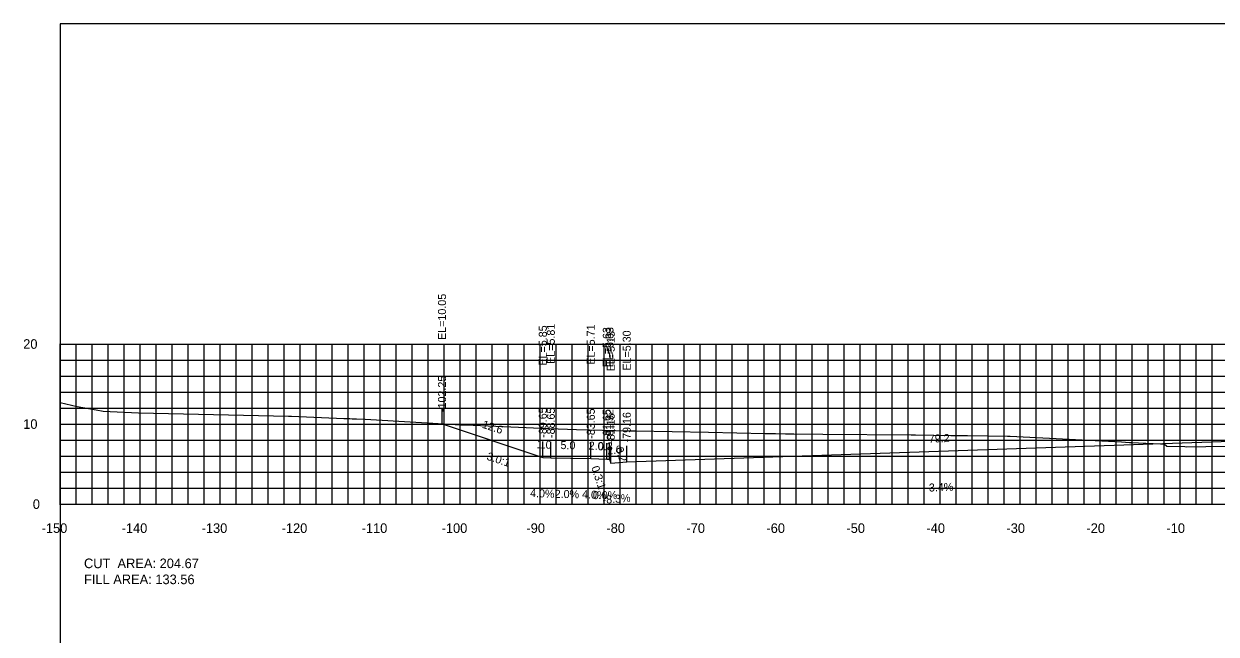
# Model space of a CAD drawing. Extents: x 1797419 to 1809236, y 248759 to 251512.
# Drawn here: x 1805876.5 to 1806025.5, y 250531 to 250607.3 of the extents above; entities that cross this region are included whole.
import ezdxf

# ---------------------------------------------------------------- set-up
doc = ezdxf.new("R2010")
doc.units = 0
for name, color, linetype in [('10', 7, 'Continuous'), ('3', 7, 'Continuous'), ('31', 7, 'Continuous'), ('4', 7, 'Continuous'), ('60', 7, 'Continuous'), ('ANNO-TXT', 7, 'Continuous'), ('CL-CNST', 7, 'Continuous'), ('Level 62', 7, 'Continuous'), ('M-ROADS', 7, 'Continuous')]:
    doc.layers.add(name, color=color, linetype=linetype)

msp = doc.modelspace()

# ---------------------------------------------------------------- linework, layer by layer
for p, q in [((1805928.75, 250557.3), (1805928.75, 250559.3)), ((1805941.35, 250553.1), (1805941.35, 250555.1)), ((1805942.35, 250553.06), (1805942.35, 250555.06)), ((1805947.35, 250552.96), (1805947.35, 250554.96)), ((1805949.35, 250552.88), (1805949.35, 250554.88)), ((1805949.68, 250552.88), (1805949.68, 250554.88)), ((1805951.84, 250552.55), (1805951.84, 250554.55)), ((1805949.84, 250552.38), (1805949.84, 250554.38))]:
    msp.add_line(p, q)
msp.add_lwpolyline([(1805881, 250417.26), (1806181, 250417.26), (1806181, 250607.26), (1805881, 250607.26)], close=True)
at = {"layer": '60'}
for p, q in [((1805880.94, 250567.26), (1805881, 250567.26)), ((1805881, 250547.26), (1805881, 250567.26)), ((1805880.94, 250557.26), (1805881, 250557.26)), ((1805880.94, 250547.26), (1805881, 250547.26)), ((1805881, 250547.26), (1806181, 250547.26)), ((1805881, 250547.2), (1805881, 250547.26)), ((1805891, 250547.2), (1805891, 250547.26)), ((1805901, 250547.2), (1805901, 250547.26)), ((1805911, 250547.2), (1805911, 250547.26)), ((1805921, 250547.2), (1805921, 250547.26)), ((1805931, 250547.2), (1805931, 250547.26)), ((1805941, 250547.2), (1805941, 250547.26)), ((1805951, 250547.2), (1805951, 250547.26)), ((1805961, 250547.2), (1805961, 250547.26)), ((1805971, 250547.2), (1805971, 250547.26)), ((1805981, 250547.2), (1805981, 250547.26)), ((1805991, 250547.2), (1805991, 250547.26)), ((1806001, 250547.2), (1806001, 250547.26)), ((1806011, 250547.2), (1806011, 250547.26)), ((1806021, 250547.2), (1806021, 250547.26))]:
    msp.add_line(p, q, dxfattribs=at)
at = {"layer": 'CL-CNST'}
msp.add_lwpolyline([(1805928.75, 250557.3), (1805941.35, 250553.1), (1805942.35, 250553.06), (1805947.35, 250552.96), (1805949.35, 250552.88), (1805949.68, 250552.88), (1805949.84, 250552.38), (1805951.84, 250552.55), (1806031, 250555.24), (1806097.41, 250557.49), (1806099.41, 250557.32), (1806099.57, 250557.82), (1806099.9, 250557.82), (1806101.9, 250557.9), (1806106.9, 250558), (1806107.9, 250558.04), (1806114.23, 250555.93)], dxfattribs=at)
at = {"layer": 'Level 62'}
for p, q in [((1805881, 250567.26), (1806181, 250567.26)), ((1805881, 250547.26), (1805881, 250567.26)), ((1805883, 250547.26), (1805883, 250567.26)), ((1805885, 250547.26), (1805885, 250567.26)), ((1805887, 250547.26), (1805887, 250567.26)), ((1805889, 250547.26), (1805889, 250567.26)), ((1805891, 250547.26), (1805891, 250567.26)), ((1805893, 250547.26), (1805893, 250567.26)), ((1805895, 250547.26), (1805895, 250567.26)), ((1805897, 250547.26), (1805897, 250567.26)), ((1805899, 250547.26), (1805899, 250567.26)), ((1805901, 250547.26), (1805901, 250567.26)), ((1805903, 250547.26), (1805903, 250567.26)), ((1805905, 250547.26), (1805905, 250567.26)), ((1805907, 250547.26), (1805907, 250567.26)), ((1805909, 250547.26), (1805909, 250567.26)), ((1805911, 250547.26), (1805911, 250567.26)), ((1805913, 250547.26), (1805913, 250567.26)), ((1805915, 250547.26), (1805915, 250567.26)), ((1805917, 250547.26), (1805917, 250567.26)), ((1805919, 250547.26), (1805919, 250567.26)), ((1805921, 250547.26), (1805921, 250567.26)), ((1805923, 250547.26), (1805923, 250567.26)), ((1805925, 250547.26), (1805925, 250567.26)), ((1805927, 250547.26), (1805927, 250567.26)), ((1805929, 250547.26), (1805929, 250567.26)), ((1805931, 250547.26), (1805931, 250567.26)), ((1805933, 250547.26), (1805933, 250567.26)), ((1805935, 250547.26), (1805935, 250567.26)), ((1805937, 250547.26), (1805937, 250567.26)), ((1805939, 250547.26), (1805939, 250567.26)), ((1805941, 250547.26), (1805941, 250567.26)), ((1805943, 250547.26), (1805943, 250567.26)), ((1805945, 250547.26), (1805945, 250567.26)), ((1805947, 250547.26), (1805947, 250567.26)), ((1805949, 250547.26), (1805949, 250567.26)), ((1805951, 250547.26), (1805951, 250567.26)), ((1805953, 250547.26), (1805953, 250567.26)), ((1805955, 250547.26), (1805955, 250567.26)), ((1805957, 250547.26), (1805957, 250567.26)), ((1805959, 250547.26), (1805959, 250567.26)), ((1805961, 250547.26), (1805961, 250567.26)), ((1805963, 250547.26), (1805963, 250567.26)), ((1805965, 250547.26), (1805965, 250567.26)), ((1805967, 250547.26), (1805967, 250567.26)), ((1805969, 250547.26), (1805969, 250567.26)), ((1805971, 250547.26), (1805971, 250567.26)), ((1805973, 250547.26), (1805973, 250567.26)), ((1805975, 250547.26), (1805975, 250567.26)), ((1805977, 250547.26), (1805977, 250567.26)), ((1805979, 250547.26), (1805979, 250567.26)), ((1805981, 250547.26), (1805981, 250567.26)), ((1805983, 250547.26), (1805983, 250567.26)), ((1805985, 250547.26), (1805985, 250567.26)), ((1805987, 250547.26), (1805987, 250567.26)), ((1805989, 250547.26), (1805989, 250567.26)), ((1805991, 250547.26), (1805991, 250567.26)), ((1805993, 250547.26), (1805993, 250567.26)), ((1805995, 250547.26), (1805995, 250567.26)), ((1805997, 250547.26), (1805997, 250567.26)), ((1805999, 250547.26), (1805999, 250567.26)), ((1806001, 250547.26), (1806001, 250567.26)), ((1806003, 250547.26), (1806003, 250567.26)), ((1806005, 250547.26), (1806005, 250567.26)), ((1806007, 250547.26), (1806007, 250567.26)), ((1806009, 250547.26), (1806009, 250567.26)), ((1806011, 250547.26), (1806011, 250567.26)), ((1806013, 250547.26), (1806013, 250567.26)), ((1806015, 250547.26), (1806015, 250567.26)), ((1806017, 250547.26), (1806017, 250567.26)), ((1806019, 250547.26), (1806019, 250567.26)), ((1806021, 250547.26), (1806021, 250567.26)), ((1806023, 250547.26), (1806023, 250567.26)), ((1806025, 250547.26), (1806025, 250567.26)), ((1805881, 250565.26), (1806181, 250565.26)), ((1805881, 250563.26), (1806181, 250563.26)), ((1805881, 250561.26), (1806181, 250561.26)), ((1805881, 250559.26), (1806181, 250559.26)), ((1805881, 250557.26), (1806181, 250557.26)), ((1805881, 250555.26), (1806181, 250555.26)), ((1805881, 250553.26), (1806181, 250553.26)), ((1805881, 250551.26), (1806181, 250551.26)), ((1805881, 250549.26), (1806181, 250549.26)), ((1805881, 250547.26), (1806181, 250547.26))]:
    msp.add_line(p, q, dxfattribs=at)
at = {"layer": 'M-ROADS'}
msp.add_lwpolyline([(1805881, 250559.95), (1805883.15, 250559.47), (1805885.53, 250559.02), (1805886.38, 250558.87), (1805890.82, 250558.65), (1805909.56, 250558.23), (1805909.7, 250558.23), (1805909.93, 250558.23), (1805916.46, 250557.97), (1805917.21, 250557.94), (1805917.23, 250557.94), (1805917.51, 250557.93), (1805917.52, 250557.93), (1805918.07, 250557.93), (1805919.15, 250557.86), (1805931.11, 250557.16), (1805931.44, 250557.16), (1805931.67, 250557.16), (1805941.13, 250556.75), (1805941.78, 250556.73), (1805942.16, 250556.71), (1805945.56, 250556.6), (1805952.04, 250556.43), (1805952.6, 250556.43), (1805952.99, 250556.42), (1805962.05, 250556.26), (1805969.16, 250556.1), (1805969.42, 250556.09), (1805970.44, 250556.07), (1805971.69, 250556.04), (1805972.15, 250556.03), (1805972.69, 250556.03), (1805972.73, 250556.03), (1805976.36, 250555.99), (1805987.41, 250555.9), (1805987.84, 250555.9), (1805987.95, 250555.9), (1805992.35, 250555.84), (1805992.69, 250555.83), (1805993.29, 250555.83), (1805993.99, 250555.85), (1805994.43, 250555.84), (1805999.45, 250555.75), (1805999.78, 250555.75), (1806013.67, 250555.02), (1806014.69, 250554.96), (1806014.91, 250554.96), (1806018.56, 250554.78), (1806018.56, 250554.79), (1806018.66, 250554.78), (1806019.03, 250554.79), (1806019.33, 250554.49), (1806021.58, 250554.46), (1806021.82, 250554.43), (1806029.11, 250554.55)], dxfattribs=at)

# ---------------------------------------------------------------- texts
for s, rotation, p in [('3.0:1', 341.5651, (1805934.26, 250552.83)), ('0.3:1', 288.4353, (1805947.39, 250551.84))]:
    msp.add_text(s, height=1, rotation=rotation).set_placement(p)
at = {"layer": '10'}
for s, p in [('-150', (1805878.7, 250543.66)), ('-140', (1805888.7, 250543.66)), ('-130', (1805898.7, 250543.66)), ('-120', (1805908.7, 250543.66)), ('-110', (1805918.7, 250543.66)), ('-100', (1805928.7, 250543.66)), ('-90', (1805939.3, 250543.66)), ('-80', (1805949.3, 250543.66)), ('-70', (1805959.3, 250543.66)), ('-60', (1805969.3, 250543.66)), ('-50', (1805979.3, 250543.66)), ('-40', (1805989.3, 250543.66)), ('-30', (1805999.3, 250543.66)), ('-20', (1806009.3, 250543.66)), ('-10', (1806019.3, 250543.66))]:
    msp.add_text(s, height=1.2, dxfattribs=at).set_placement(p)
at = {"layer": '3'}
for s, p in [('EL=10.05', (1805929.25, 250567.77)), ('EL=5.85', (1805941.85, 250564.57)), ('EL=5.81', (1805942.85, 250564.78)), ('EL=5.71', (1805947.85, 250564.68)), ('EL=5.63', (1805949.85, 250564.35)), ('EL=5.63', (1805950.18, 250564.35)), ('EL=5.13', (1805950.34, 250563.85)), ('EL=5.30', (1805952.34, 250563.94)), ('-102.25', (1805929.25, 250558.77)), ('-89.65', (1805941.85, 250555.56)), ('-88.65', (1805942.85, 250555.52)), ('-83.65', (1805947.85, 250555.42)), ('-81.65', (1805949.85, 250555.34)), ('-81.32', (1805950.18, 250555.34)), ('-81.16', (1805950.34, 250554.79)), ('-79.16', (1805952.34, 250554.96))]:
    msp.add_text(s, height=1, rotation=90, dxfattribs=at).set_placement(p)
at = {"layer": '31'}
for s, p in [('20', (1805876.4, 250566.66)), ('10', (1805876.4, 250556.66)), ('0', (1805877.6, 250546.66))]:
    msp.add_text(s, height=1.2, dxfattribs=at).set_placement(p)
at = {"layer": '4'}
for s, rotation, p in [('12.6', 341.5651, (1805933.69, 250556.82)), ('79.2', 1.9432, (1805989.61, 250554.93)), ('1.0', 357.7094, (1805940.57, 250554.24)), ('5.0', 358.8542, (1805943.55, 250554.14)), ('2.0', 357.7094, (1805947.07, 250554.08)), ('2.0', 4.7636, (1805949.43, 250553.45)), ('0.2', 288.4353, (1805950.4, 250554.2)), ('4.0%', 357.7094, (1805939.74, 250548.16)), ('2.0%', 358.8542, (1805942.83, 250548.05)), ('4.0%', 357.7094, (1805946.24, 250548)), ('-8.3%', 4.7636, (1805948.86, 250547.28)), ('-3.4%', 1.9432, (1805989.18, 250548.81))]:
    msp.add_text(s, height=1, rotation=rotation, dxfattribs=at).set_placement(p)
for s, p in [('0.3', (1805948.23, 250553.98)), ('0.0%', (1805947.6, 250547.88))]:
    msp.add_text(s, height=1, dxfattribs=at).set_placement(p)
at = {"layer": '60'}
msp.add_text('-', height=0.0001, dxfattribs=at).set_placement((1805881, 250547.26))
at = {"layer": 'ANNO-TXT'}
for s, p in [('CUT  AREA: 204.67', (1805884, 250539.26)), ('FILL AREA: 133.56', (1805884, 250537.26))]:
    msp.add_text(s, height=1.2, dxfattribs=at).set_placement(p)

doc.saveas('drawing.dxf')
